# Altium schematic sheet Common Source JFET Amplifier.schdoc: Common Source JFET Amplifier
size A4; Organization: Altium Limited; Address1: L3, 12a Rodborough Rd; Address2: Frenchs Forest; Address3: NSW; Address4: Australia 2086; DocumentNumber: 1; SheetNumber: 1; SheetTotal: 1
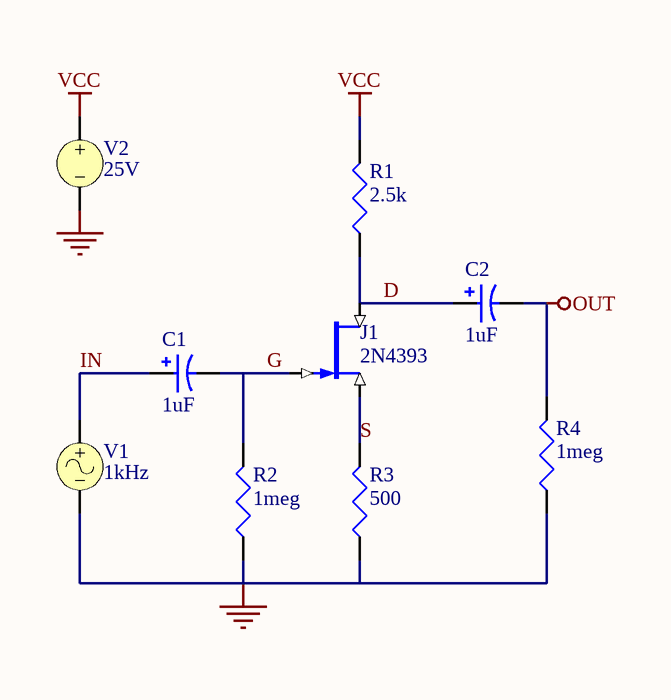
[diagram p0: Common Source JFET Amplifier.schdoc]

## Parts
C1  1uF
C2  1uF
J1  2N4393
R1  2.5k
R2  1meg
R3  500
R4  1meg
V1  1kHz
V2  25V

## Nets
GND: R2.2(BOT) R3.2(BOT) R4.2(BOT) V1.2 V2.2
OUT: C2.2 R4.1(TOP)
VCC: R1.1(TOP) V2.1
D: C2.1 J1.1(D) R1.2(BOT)
G: C1.2 J1.2(G) R2.1(TOP)
IN: C1.1 V1.1
S: J1.3(S) R3.1(TOP)

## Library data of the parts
C1 C2 = CAP2: Bi-Polar Capacitor
J1 = 2N4393: N-Channel JFET
R1-R4 = RES: Resistor
V1 = VSIN: Sinusoidal Voltage Source
V2 = VSRC: Voltage Source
